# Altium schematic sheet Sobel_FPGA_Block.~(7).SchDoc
size A2
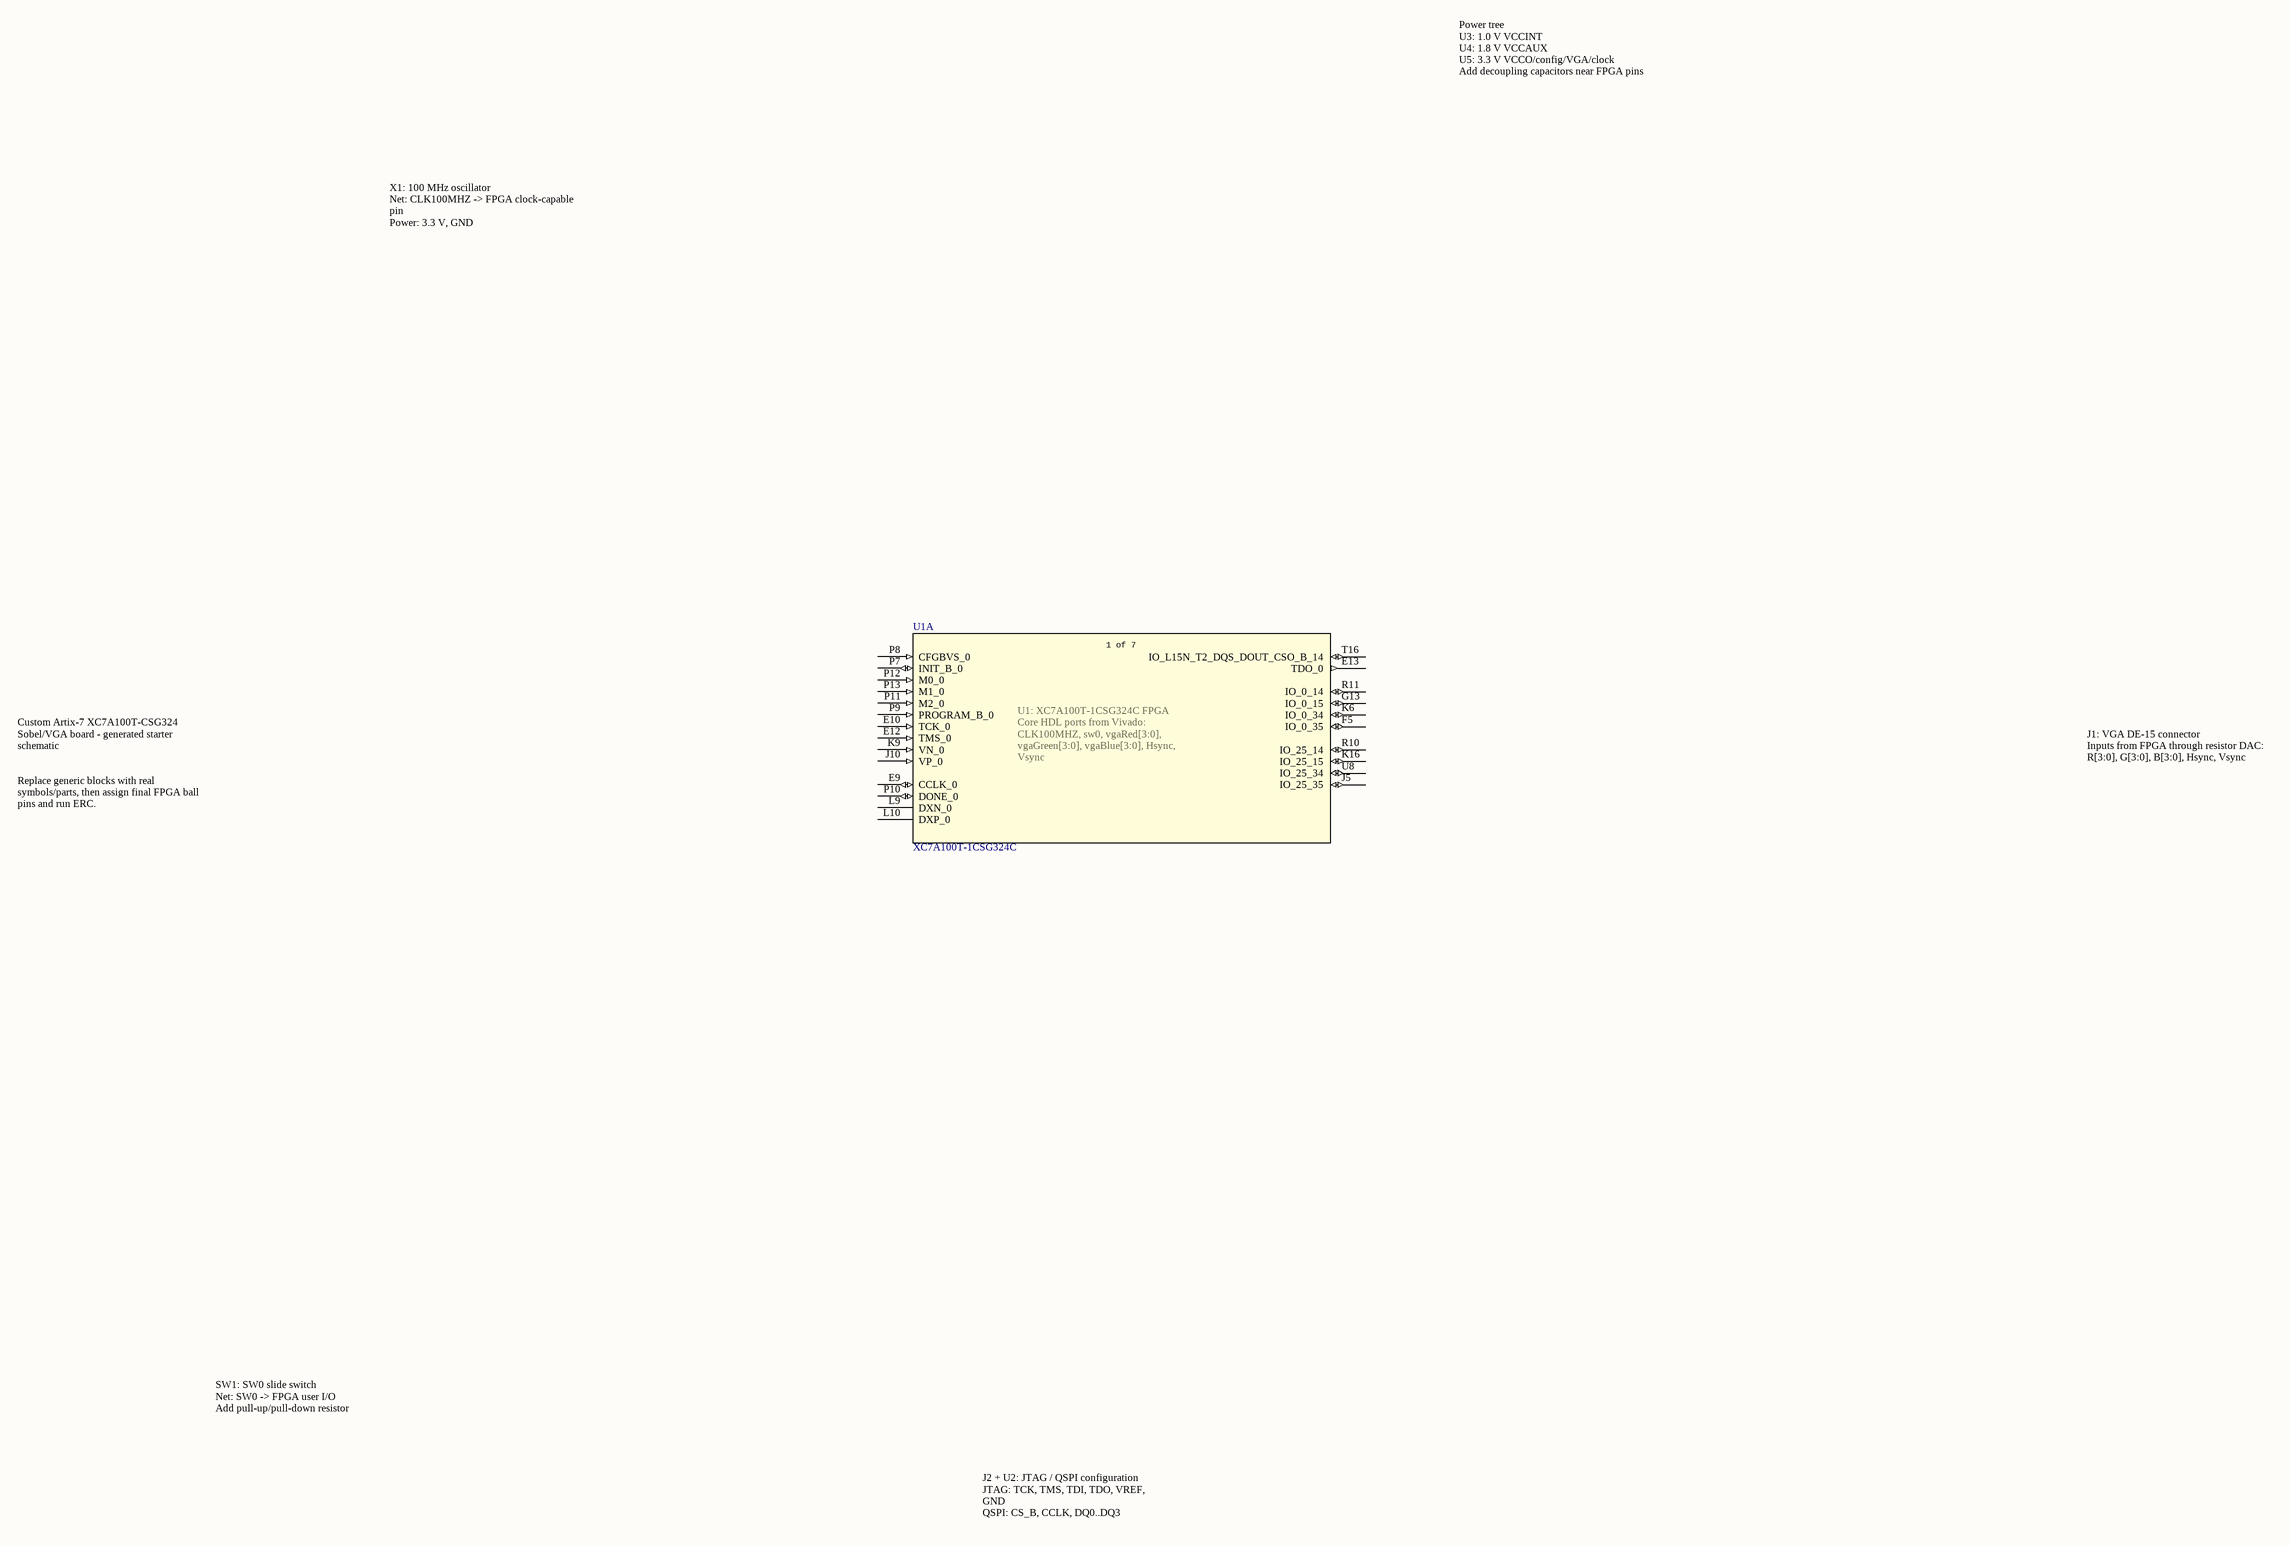
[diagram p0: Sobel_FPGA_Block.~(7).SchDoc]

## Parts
U1  XC7A100T-1CSG324C  [CSG324_XIL]  (part A of 7)

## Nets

Not connected (* = marked no-connect by the designer): U1 E9(CCLK_0) E10(TCK_0) E12(TMS_0) E13(TDO_0) F5(IO_0_35) G13(IO_0_15) J5(IO_25_35) J10(VP_0) K6(IO_0_34) K9(VN_0) K16(IO_25_15) L9(DXN_0) L10(DXP_0) P7(INIT_B_0) P8(CFGBVS_0) P9(PROGRAM_B_0) P10(DONE_0) P11(M2_0) P12(M0_0) P13(M1_0) R10(IO_25_14) R11(IO_0_14) T16(IO_L15N_T2_DQS_DOUT_CSO_B_14) U8(IO_25_34)

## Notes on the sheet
- Power tree
  U3: 1.0 V VCCINT
  U4: 1.8 V VCCAUX
  U5: 3.3 V VCCO/config/VGA/clock
  Add decoupling capacitors near FPGA pins
- X1: 100 MHz oscillator
  Net: CLK100MHZ -> FPGA clock-capable pin
  Power: 3.3 V, GND
- Custom Artix-7 XC7A100T-CSG324 Sobel/VGA board - generated starter schematic
- (near U1) U1: XC7A100T-1CSG324C FPGA
  Core HDL ports from Vivado:
  CLK100MHZ, sw0, vgaRed[3:0], vgaGreen[3:0], vgaBlue[3:0], Hsync, Vsync
- J1: VGA DE-15 connector
  Inputs from FPGA through resistor DAC:
  R[3:0], G[3:0], B[3:0], Hsync, Vsync
- Replace generic blocks with real symbols/parts, then assign final FPGA ball pins and run ERC.
- SW1: SW0 slide switch
  Net: SW0 -> FPGA user I/O
  Add pull-up/pull-down resistor
- J2 + U2: JTAG / QSPI configuration
  JTAG: TCK, TMS, TDI, TDO, VREF, GND
  QSPI: CS_B, CCLK, DQ0..DQ3

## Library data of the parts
U1 = XC7A100T-1CSG324C: Description; Manufacturer_Name: Xilinx Inc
